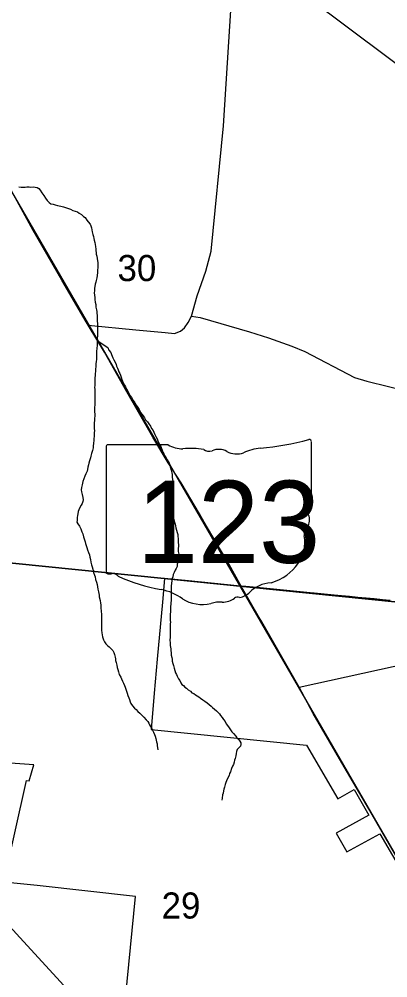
# Model space of a CAD drawing. Extents: x -7.3 to 34, y 0 to 22.
# Drawn here: x 6.729 to 7.321, y 15.258 to 16.795 of the extents above; entities that cross this region are included whole.
import ezdxf

# ---------------------------------------------------------------- set-up
doc = ezdxf.new("R2010")
doc.units = 0
for name, color, linetype in [('GM_X_City_Street', 7, 'Continuous'), ('GM_X_Corporation', 7, 'Continuous'), ('GM_X_County_Road', 7, 'Continuous'), ('GM_X_Minor_River', 7, 'Continuous'), ('GM_X_Rail_Line', 7, 'Continuous'), ('GM_X_Section_Text', 7, 'Continuous'), ('GM_X_State_Location', 7, 'Continuous'), ('GM_X_State_Route', 7, 'Continuous'), ('GM_X_State_Shield', 7, 'Continuous'), ('GM_X_Township_Road', 7, 'Continuous'), ('SH_Text', 7, 'Continuous')]:
    doc.layers.add(name, color=color, linetype=linetype)

msp = doc.modelspace()

# ---------------------------------------------------------------- linework, layer by layer
at = {"layer": 'GM_X_City_Street'}
for points in [[(7.0054, 16.3187), (7.0146, 16.3514), (7.0285, 16.3908), (7.0368, 16.423), (7.0569, 16.6243), (7.0755, 16.9195), (7.0777, 16.943), (7.0808, 16.9642), (7.0904, 16.9899)], [(6.8397, 16.3042), (6.9163, 16.2969), (6.9632, 16.2927), (6.978, 16.2913), (6.9879, 16.2949), (6.9944, 16.3002), (7, 16.3085), (7.0054, 16.3187), (7.0196, 16.3167), (7.0985, 16.2937), (7.1289, 16.2841), (7.1663, 16.2709), (7.1875, 16.2621), (7.2672, 16.2205), (7.2871, 16.2145), (7.4609, 16.1716), (7.515, 16.1606)]]:
    msp.add_lwpolyline(points, dxfattribs=at)
at = {"layer": 'GM_X_Corporation'}
for points in [[(7.5781, 16.8709), (7.4799, 15.8457), (6.4371, 15.9508), (6.5281, 16.9583)], [(6.4371, 15.9508), (7.4799, 15.8457), (7.3939, 14.8252), (6.3438, 14.9266)]]:
    msp.add_lwpolyline(points, close=True, dxfattribs=at)
for points in [[(7.3244, 15.8629), (7.312, 15.864), (7.2988, 15.8653), (7.2856, 15.8665), (7.2724, 15.8677), (7.2592, 15.869), (7.2463, 15.8702), (7.246, 15.8702), (7.2343, 15.8713), (7.2025, 15.8743), (7.1959, 15.8749), (7.1105, 15.8835), (7.0928, 15.8851), (7.0859, 15.8857), (7.079, 15.8864), (7.0009, 15.8942), (6.9623, 15.8981), (6.9587, 15.8601), (6.9506, 15.7685), (6.9458, 15.7141), (6.9409, 15.6559), (7.1899, 15.6305), (7.2401, 15.5445), (7.2665, 15.5596), (7.2903, 15.5185), (7.2374, 15.4894), (7.2548, 15.4594), (7.3075, 15.4887), (7.3926, 15.3428)], [(6.8943, 15.1697), (6.9158, 15.3877), (6.7577, 15.4057), (6.7044, 15.4109), (6.7404, 15.5743), (6.7449, 15.5736), (6.7526, 15.5989), (6.5186, 15.6157)]]:
    msp.add_lwpolyline(points, dxfattribs=at)
at = {"layer": 'GM_X_County_Road'}
msp.add_lwpolyline([(5.9101, 15.654), (6.405, 15.6216), (6.39, 15.4485), (6.3969, 15.4388), (6.6396, 15.4146), (6.6541, 15.4047), (7.0106, 15.016), (7.0281, 15.003), (7.4002, 14.9537)], dxfattribs=at)
at = {"layer": 'GM_X_Minor_River'}
for points in [[(6.7284, 16.5264), (6.7322, 16.526), (6.736, 16.5259), (6.7386, 16.5258), (6.7413, 16.5262), (6.7447, 16.5261), (6.7477, 16.526), (6.7515, 16.5263), (6.7546, 16.5259), (6.7576, 16.5254), (6.7606, 16.5238), (6.7628, 16.5211), (6.765, 16.5169), (6.7683, 16.5126), (6.7709, 16.5084), (6.7738, 16.5045), (6.7771, 16.5011), (6.7798, 16.4991), (6.7832, 16.4983), (6.7866, 16.4974), (6.7903, 16.4962)], [(6.7903, 16.4962), (6.793, 16.4958), (6.796, 16.4953), (6.7998, 16.4941), (6.8031, 16.4933), (6.808, 16.4916), (6.8114, 16.4904), (6.8152, 16.4884), (6.8186, 16.4872), (6.8223, 16.486), (6.8253, 16.484), (6.8287, 16.4821), (6.832, 16.479), (6.8347, 16.477), (6.8376, 16.4731), (6.8398, 16.47), (6.8428, 16.4666), (6.8439, 16.4639), (6.8449, 16.4608), (6.8463, 16.4543), (6.8473, 16.4501), (6.848, 16.4467), (6.8487, 16.4433), (6.8494, 16.4406), (6.8501, 16.4368), (6.8508, 16.4341), (6.8515, 16.4307), (6.8518, 16.4265), (6.8521, 16.4238), (6.8524, 16.4208), (6.8527, 16.4181), (6.8534, 16.415), (6.8541, 16.4112), (6.8548, 16.4078), (6.8551, 16.4051), (6.8554, 16.4017), (6.8553, 16.399), (6.8553, 16.3964), (6.8548, 16.393), (6.8544, 16.3888), (6.8539, 16.3842), (6.8534, 16.3801), (6.8526, 16.3763), (6.8521, 16.3733), (6.8509, 16.3703), (6.8505, 16.3665), (6.8496, 16.3638), (6.8496, 16.36), (6.8495, 16.3558), (6.8498, 16.3532), (6.8501, 16.3482), (6.8504, 16.3456), (6.851, 16.3414), (6.8517, 16.3376), (6.852, 16.3334), (6.8531, 16.3292), (6.8534, 16.3261), (6.8537, 16.3235), (6.854, 16.32), (6.8539, 16.3166), (6.8542, 16.3139), (6.8542, 16.3113), (6.8545, 16.3067), (6.8548, 16.3029), (6.8547, 16.2991), (6.8546, 16.2942), (6.8545, 16.2911), (6.8544, 16.2866), (6.8543, 16.2839), (6.8543, 16.2801), (6.8542, 16.2763), (6.8541, 16.2722), (6.8536, 16.2668), (6.8531, 16.2627), (6.8531, 16.26), (6.853, 16.2566), (6.8529, 16.2536), (6.8528, 16.2494), (6.8524, 16.246), (6.8519, 16.2422), (6.8518, 16.238), (6.8514, 16.2338), (6.8513, 16.2304), (6.8508, 16.2266), (6.8508, 16.224), (6.8503, 16.2194), (6.8502, 16.2156), (6.8501, 16.2118), (6.8504, 16.2076), (6.85, 16.2046), (6.8503, 16.2016), (6.8502, 16.1982), (6.8501, 16.194), (6.8504, 16.1886), (6.8503, 16.1849), (6.8502, 16.1811), (6.8501, 16.1761), (6.85, 16.1727), (6.85, 16.1693), (6.8499, 16.1655), (6.8502, 16.1617)], [(6.8543, 16.2801), (6.8711, 16.2684), (6.8729, 16.2645), (6.8758, 16.2607), (6.8773, 16.2576), (6.8784, 16.2545), (6.8794, 16.2518), (6.8809, 16.2488), (6.8827, 16.2453), (6.8845, 16.2415), (6.8852, 16.2388), (6.8867, 16.2354), (6.8877, 16.2327), (6.8888, 16.2296), (6.8903, 16.2269), (6.8914, 16.2242), (6.8924, 16.2208), (6.8935, 16.2173), (6.8956, 16.212), (6.8978, 16.2081), (6.8993, 16.2054), (6.9011, 16.202), (6.9026, 16.1989), (6.9051, 16.1951), (6.9073, 16.1912), (6.9092, 16.1885), (6.9117, 16.1835), (6.9147, 16.1797), (6.9169, 16.1762), (6.9194, 16.1723), (6.9213, 16.1689), (6.9238, 16.1646), (6.9257, 16.1619), (6.9279, 16.1588), (6.9301, 16.1558), (6.9319, 16.1527), (6.9349, 16.1496), (6.9371, 16.1461), (6.9396, 16.1423), (6.9415, 16.1388), (6.9437, 16.1357), (6.9451, 16.1326), (6.9466, 16.1292), (6.948, 16.1261), (6.9502, 16.1223), (6.952, 16.1173), (6.9545, 16.1127), (6.956, 16.11), (6.9574, 16.1065), (6.9585, 16.1038), (6.9596, 16.1008), (6.9611, 16.0981), (6.9621, 16.0954), (6.9643, 16.0923), (6.9662, 16.0885), (6.968, 16.0858), (6.9695, 16.0831), (6.9709, 16.0793), (6.9719, 16.0754), (6.973, 16.072), (6.9737, 16.0678), (6.9744, 16.0648), (6.9747, 16.0606), (6.975, 16.0568), (6.9753, 16.0541), (6.9752, 16.0511), (6.9751, 16.0476), (6.975, 16.0431), (6.9749, 16.0393), (6.9749, 16.0359), (6.9748, 16.0324), (6.9747, 16.0286), (6.9747, 16.026), (6.9746, 16.0226), (6.9745, 16.0192), (6.9748, 16.0157), (6.9747, 16.0123), (6.9747, 16.0089), (6.975, 16.0062), (6.9753, 16.0032), (6.9756, 16.0001), (6.9759, 15.9971), (6.977, 15.9925), (6.978, 15.9883), (6.9791, 15.9852), (6.9798, 15.9826), (6.9805, 15.9795), (6.9815, 15.9757), (6.9822, 15.9719), (6.9833, 15.9684), (6.9836, 15.9654), (6.9839, 15.962), (6.9842, 15.9585), (6.9841, 15.9559), (6.9844, 15.9521), (6.9844, 15.9494), (6.9843, 15.9468)], [(6.8502, 16.1617), (6.8501, 16.1583), (6.85, 16.1552), (6.85, 16.1522), (6.8495, 16.1473), (6.8494, 16.1442), (6.8493, 16.1412), (6.8493, 16.1385), (6.8496, 16.1351), (6.8492, 16.1324), (6.8491, 16.129), (6.849, 16.1256), (6.8489, 16.1226), (6.8485, 16.1195), (6.8484, 16.1154), (6.8479, 16.1104), (6.8475, 16.1078), (6.8466, 16.1036), (6.845, 16.0987), (6.8438, 16.0942), (6.8433, 16.0915), (6.8417, 16.0866), (6.8409, 16.0829), (6.8401, 16.0802), (6.8392, 16.0764), (6.8384, 16.073), (6.8379, 16.0704), (6.8359, 16.0659), (6.8343, 16.0621), (6.8327, 16.058), (6.8311, 16.0538), (6.8303, 16.0512), (6.8299, 16.0481), (6.829, 16.044), (6.8286, 16.0402), (6.8289, 16.0371), (6.8299, 16.0326), (6.8309, 16.028), (6.8316, 16.0242), (6.8312, 16.0215), (6.83, 16.0185), (6.8284, 16.0159), (6.8264, 16.0121), (6.8244, 16.008), (6.8236, 16.0053), (6.8228, 16.0019), (6.8224, 15.9993), (6.8219, 15.9959), (6.8218, 15.9909), (6.8217, 15.9883), (6.8232, 15.9856), (6.8258, 15.9821), (6.828, 15.9779), (6.8297, 15.9729), (6.8308, 15.9695), (6.8322, 15.9649), (6.8336, 15.9599), (6.8347, 15.9568), (6.8354, 15.9542), (6.8365, 15.9511), (6.8376, 15.948), (6.8386, 15.9438), (6.8404, 15.9396), (6.8415, 15.9358), (6.8421, 15.9324), (6.8432, 15.9285), (6.8439, 15.924), (6.8449, 15.9202), (6.846, 15.9167), (6.847, 15.9129), (6.8481, 15.9079), (6.8499, 15.9033), (6.8506, 15.9007), (6.8516, 15.8965), (6.853, 15.8922), (6.8541, 15.8884), (6.8544, 15.8846), (6.8554, 15.8812), (6.8561, 15.8766), (6.8575, 15.8712), (6.8574, 15.8686), (6.8588, 15.8629), (6.8595, 15.8587), (6.8598, 15.8556), (6.8601, 15.8522), (6.8607, 15.8446), (6.861, 15.8412), (6.861, 15.8385), (6.8612, 15.8339), (6.8612, 15.8313), (6.8611, 15.8282), (6.861, 15.8248), (6.8609, 15.8203), (6.8612, 15.8153), (6.8615, 15.8111), (6.8622, 15.8077), (6.8625, 15.8047), (6.8643, 15.7997), (6.8657, 15.7966), (6.8679, 15.7935), (6.8705, 15.7904)], [(6.9843, 15.9468), (6.9843, 15.9441), (6.9842, 15.9414), (6.9849, 15.9372), (6.9852, 15.9334), (6.9847, 15.9297), (6.9838, 15.9244), (6.9826, 15.921), (6.9822, 15.9172), (6.9806, 15.9142), (6.9794, 15.9115), (6.9774, 15.9078), (6.9762, 15.9044), (6.9753, 15.901), (6.9745, 15.898), (6.9741, 15.8945), (6.9736, 15.8908), (6.9731, 15.8855), (6.973, 15.8824), (6.973, 15.8798), (6.9729, 15.876), (6.9728, 15.8729), (6.9727, 15.8684), (6.9727, 15.8657), (6.9726, 15.863), (6.9725, 15.8589), (6.9725, 15.8562), (6.972, 15.8536), (6.9719, 15.849), (6.9715, 15.8448), (6.9714, 15.841), (6.9713, 15.8365), (6.9712, 15.8308), (6.9715, 15.8281), (6.9714, 15.8251), (6.9714, 15.8224), (6.9713, 15.8194), (6.9712, 15.8148), (6.9711, 15.8114), (6.971, 15.8042), (6.9709, 15.7993), (6.9711, 15.7951), (6.9714, 15.7905), (6.9721, 15.7852), (6.9724, 15.7821), (6.9727, 15.7791), (6.973, 15.7749), (6.9737, 15.7715), (6.9744, 15.7684), (6.9747, 15.7657), (6.9757, 15.7619), (6.9764, 15.7585), (6.9778, 15.7543), (6.9789, 15.7505), (6.98, 15.747), (6.9814, 15.7439), (6.9825, 15.7413), (6.9847, 15.737), (6.9865, 15.7343), (6.9883, 15.7309), (6.9898, 15.7282), (6.9924, 15.7262), (6.9946, 15.7235), (6.9972, 15.7219), (7.0002, 15.7196), (7.0036, 15.7172), (7.0062, 15.7149), (7.0092, 15.7137), (7.0118, 15.7117), (7.0144, 15.7098), (7.0174, 15.7082), (7.02, 15.7062), (7.0234, 15.7035), (7.0268, 15.7012), (7.0305, 15.6984), (7.0338, 15.6957), (7.0368, 15.6933), (7.0394, 15.6914), (7.0424, 15.6887), (7.0454, 15.6859), (7.048, 15.6836), (7.0502, 15.6809), (7.052, 15.6782), (7.0546, 15.6751), (7.0568, 15.672), (7.0594, 15.6685), (7.0612, 15.6651), (7.0631, 15.662), (7.066, 15.6585), (7.0682, 15.6551), (7.0704, 15.652), (7.0727, 15.6493), (7.0764, 15.6454), (7.0782, 15.6427), (7.0808, 15.6403), (7.083, 15.6373), (7.0845, 15.6346), (7.0848, 15.6319), (7.084, 15.6293), (7.0816, 15.6263), (7.0789, 15.624)], [(6.8705, 15.7904), (6.8735, 15.7885), (6.8761, 15.7857), (6.8791, 15.7826), (6.8809, 15.7792), (6.882, 15.7761), (6.883, 15.7719), (6.8833, 15.7692), (6.8837, 15.7666), (6.8844, 15.7631), (6.8854, 15.7593), (6.8861, 15.7555), (6.8871, 15.7521), (6.8882, 15.7486), (6.8896, 15.744), (6.8918, 15.7398), (6.8929, 15.7371), (6.8947, 15.7333), (6.8965, 15.7302), (6.898, 15.7264), (6.899, 15.7237), (6.9005, 15.7187), (6.9022, 15.7141), (6.9033, 15.7103), (6.9047, 15.7069), (6.9058, 15.7038), (6.9069, 15.7004), (6.9083, 15.6973), (6.9109, 15.6938), (6.9139, 15.6903), (6.9165, 15.688), (6.9194, 15.6845), (6.9224, 15.6818), (6.9261, 15.6783), (6.9291, 15.6756), (6.9328, 15.6713), (6.9354, 15.6686), (6.9372, 15.6659), (6.9379, 15.6632), (6.9398, 15.6605), (6.9416, 15.6574), (6.9431, 15.6547), (6.9445, 15.6513), (6.9463, 15.6478), (6.9474, 15.6451), (6.9481, 15.6413), (6.9495, 15.636), (6.9502, 15.6329), (6.9505, 15.6299), (6.9508, 15.6268), (6.9515, 15.623)], [(7.0789, 15.624), (7.0777, 15.6207), (7.0773, 15.6176), (7.0764, 15.6135), (7.0756, 15.6093), (7.0744, 15.6067), (7.0739, 15.6036), (7.0727, 15.5999), (7.0715, 15.5969), (7.0699, 15.5935), (7.0683, 15.5882), (7.0667, 15.5852), (7.0659, 15.5822), (7.0635, 15.5773), (7.0619, 15.5735), (7.0607, 15.5709), (7.0595, 15.5675), (7.0583, 15.5633), (7.0574, 15.5599), (7.0566, 15.5573), (7.0562, 15.5539), (7.0553, 15.5512), (7.0549, 15.5459), (7.0544, 15.5425)]]:
    msp.add_lwpolyline(points, dxfattribs=at)
at = {"layer": 'GM_X_Rail_Line'}
msp.add_lwpolyline([(8.1171, 14.1), (7.77, 14.7008), (7.4272, 15.293), (6.5394, 16.8246), (6.3886, 17.0851), (6.2996, 17.2555), (6.2775, 17.3138), (6.2567, 17.3864), (6.213, 17.5514), (6.1948, 17.6035), (6.1703, 17.6358), (6.1218, 17.6697), (5.9568, 17.7678)], dxfattribs=at)
at = {"layer": 'GM_X_State_Route'}
for points in [[(6.8348, 16.3126), (6.7973, 16.3768), (6.7511, 16.4561), (6.7126, 16.5267), (6.6993, 16.5519), (6.6751, 16.5958), (6.6603, 16.6222), (6.6205, 16.6905), (6.5908, 16.736)], [(7.0181, 16.0016), (6.989, 16.0513), (6.968, 16.0836), (6.9436, 16.1246), (6.8996, 16.2015), (6.8659, 16.261), (6.8397, 16.3042), (6.8348, 16.3126)], [(7.0832, 15.8894), (7.0658, 15.9203), (7.0589, 15.9325), (7.0257, 15.9885), (7.0181, 16.0016)], [(7.1181, 15.8285), (7.1126, 15.8381), (7.088, 15.8808), (7.0832, 15.8894)], [(7.4344, 15.2802), (7.4005, 15.3393), (7.3473, 15.4297), (7.2956, 15.5194), (7.2506, 15.5959), (7.2007, 15.6815), (7.1784, 15.724), (7.1181, 15.8285)]]:
    msp.add_lwpolyline(points, dxfattribs=at)
at = {"layer": 'GM_X_State_Shield'}
for p, q in [((7.1979, 16.0129), (7.1979, 16.1175)), ((6.8683, 16.1091), (6.8683, 15.909)), ((6.9681, 16.1126), (6.8715, 16.1126)), ((7.1979, 16.0129), (7.1979, 16.0129))]:
    msp.add_line(p, q, dxfattribs=at)
for centre, major_axis, start_param, end_param in [((7.0805, 16.3854), (0.3495, 0), 4.814394, 5.042369), ((7.1942, 16.118), (0.00367, 0), 6.141152, 7.989035), ((6.8721, 16.1096), (0.00382, 0), 1.712693, 3.28349), ((6.9911, 16.1358), (0.037, 0), 4.042523, 4.731795), ((7.0033, 16.0002), (0.133, 0), 1.404758, 1.657858), ((7.0335, 16.1106), (0.0107, 0), 3.836095, 5.185415), ((7.0492, 16.0875), (0.0222, 0), 0.950623, 2.079405), ((7.0779, 16.1192), (0.0267, 0), 4.081561, 5.145723), ((7.1251, 16.0515), (0.0703, 0), 1.699011, 2.107814), ((7.197, 16.0052), (0.00568, 0), 1.883978, 3.671073), ((7.194, 16.0125), (0.00393, 0), 5.05454, 6.418171), ((7.1609, 15.9919), (0.0341, 0), 5.934695, 6.695948), ((7.211, 15.9691), (0.0248, 0), 2.387724, 3.262537), ((7.1001, 15.9557), (0.0874, 0), 5.101752, 6.440018), ((6.8721, 15.9086), (0.00385, 0), 3.00124, 4.508301), ((6.8727, 15.9291), (0.0294, 0), 4.665946, 4.897461), ((6.8787, 15.8975), (0.0106, 0), 0.519207, 1.627899), ((7.0125, 16.0773), (0.2524, 0), 4.195997, 4.488961), ((7.1369, 15.8528), (0.0479, 0), 1.647645, 2.488434), ((6.9373, 15.8191), (0.079, 0), 0.823519, 1.323587), ((7.0763, 15.8896), (0.0282, 0), 4.937069, 5.64225), ((7.0227, 15.8965), (0.0501, 0), 4.026481, 4.996735), ((7.0517, 15.8273), (0.0412, 0), 1.495662, 1.94098), ((7.0553, 15.8815), (0.0267, 0), 4.691044, 5.507374), ((7.0795, 15.8621), (0.00752, 0), 1.147584, 2.315152)]:
    msp.add_ellipse(centre, major_axis=major_axis, ratio=0.8, start_param=start_param, end_param=end_param, dxfattribs=at)
at = {"layer": 'GM_X_Township_Road'}
msp.add_line((7.1784, 15.724), (7.3824, 15.7687), dxfattribs=at)
at = {"layer": 'SH_Text'}
msp.add_lwpolyline([(9.4026, 15.1778), (9.4027, 15.4673), (5.869, 17.8194)], close=True, dxfattribs=at)

# ---------------------------------------------------------------- texts
at = {"layer": 'GM_X_Section_Text'}
for s, p in [('30', (6.8867, 16.3751)), ('29', (6.9575, 15.3526))]:
    msp.add_text(s, height=0.04186, rotation=0, dxfattribs=at).set_placement(p)
at = {"layer": 'GM_X_State_Location'}
for s in ['s', 'r']:
    msp.add_text(s, height=0.000189, dxfattribs=at).set_placement((7.0294, 15.9958))
msp.add_text('123', height=0.000189, rotation=0, dxfattribs=at).set_placement((6.9625, 15.982))
at = {"layer": 'GM_X_State_Shield'}
msp.add_text('123', height=0.13184, dxfattribs=at).set_placement((6.9178, 15.9231))

doc.saveas('drawing.dxf')
